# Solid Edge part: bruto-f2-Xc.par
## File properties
Author: dalbe
Template: Iso Metric Part.par
Last saved by: dalbe
Revision: 3
Application: Solid Edge
Username: dalbe
Tipo de Conteúdo do Documento: 0
Accuracy: 0,990
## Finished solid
Body 1: sheet body, 1 face, 10 edges, 10 vertices.
  Faces by surface: plane 1
  Edges by curve: line 10
Body 2: solid body, 6 faces, 5 edges, 0 vertices.
  Faces by surface: plane 3, cylinder 2, cone 1
  Edges by curve: circle 5
Bounding box of the edges (mm): 59.000 x 51.000 x 51.000, from (-59, -25.5, -25.5) to (0, 25.5, 25.5).
Cylindrical faces by radius (mm): R23 x1, R25.5 x1
Conical faces (half-angle, radius in mm at the cone's reference point): 45 deg R23 x1
Planar faces by outward normal: +x 1, -x 2
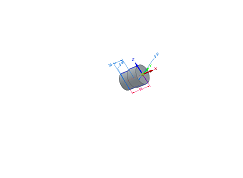
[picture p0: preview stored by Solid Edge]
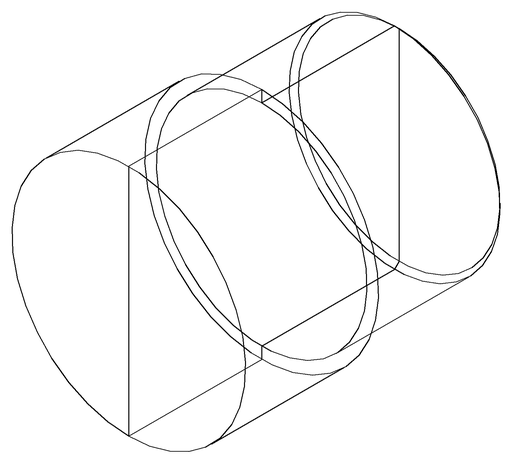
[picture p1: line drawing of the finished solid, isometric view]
